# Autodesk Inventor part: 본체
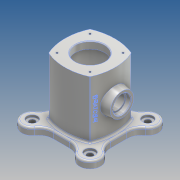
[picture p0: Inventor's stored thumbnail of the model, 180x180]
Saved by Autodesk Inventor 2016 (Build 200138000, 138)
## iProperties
Created: 2016-05
Part Number: 본체
Material: 알루미늄 6061
Document SubType Name: Modeling
Designer: Administrator
Density: 2.7 g/cm^3
Appearance: 알루미늄 - 평지
Mass: 1101.94 g
Surface Area: 864.846 cm^2
Volume: 408.127 cm^3
Author: Administrator
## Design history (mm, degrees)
sketch "스케치1" dims "d0" = 140
  geometry: L1 (-49, 49)-(49, 49); L2 (49, 49)-(49, -49); L3 (49, -49)-(-49, -49); L4 (-49, -49)-(-49, 49); L5 (-49, 49)-(49, -49); L6 (49, 49)-(-49, -49); L7 (0, 0)-(0, 49); L8 (0, 0)-(107.625, 107.625); L9 (0, 0)-(-94.165, 94.165); L10 (0, 0)-(-132.775, -132.775); L11 (0, 0)-(113.13, -113.13); L12 (0, 0)-(0, -49); A1 r 18 centre (49.497, 49.497) between (59.754, 34.706) and (34.706, 59.754); A2 r 18 centre (-49.497, 49.497) between (-34.706, 59.754) and (-59.754, 34.706); A3 r 18 centre (-49.497, -49.497) between (-59.754, -34.706) and (-34.706, -59.754); A4 r 18 centre (49.497, -49.497) between (34.706, -59.754) and (59.754, -34.706); A5 r 25 centre (-74, 14.162) between (-49, 14.162) and (-60.503, 35.205); A6 r 25 centre (-74, -14.162) between (-60.503, -35.205) and (-49, -14.162); A7 r 25 centre (-14.162, -74) between (-14.162, -49) and (-35.205, -60.503); A8 r 25 centre (14.162, -74) between (35.205, -60.503) and (14.162, -49); A9 r 25 centre (74, -14.162) between (49, -14.162) and (60.503, -35.205); A10 r 25 centre (74, 14.162) between (60.503, 35.205) and (49, 14.162); A11 r 25 centre (14.162, 74) between (14.162, 49) and (35.205, 60.503); A12 r 25 centre (-14.162, 74) between (-35.205, 60.503) and (-14.162, 49); 1 further point
  constraints: 32 point on circle, 24 end point, 16 tangent, 12 centre point, 12 point on line, 4 midpoint, 2 parallel, 1 coincident, 1 horizontal, 1 perpendicular, 14 other
  dimensions: "d1" = 98 distance of L2.end L3.end; "d2" = 98 distance of L1.end L2.end; "d5" = 45 deg angle of L7 L8; "d6" = 45 deg angle of L9 L7; "d7" = 36 diameter of A1; "d8" = 36 diameter of A2; "d9" = 45 deg angle of L10 L12; "d10" = 45 deg angle of L12 L11; "d11" = 36 diameter of A3; "d12" = 36 diameter of A4; "d13" = 50 diameter of A5; "d14" = 50 diameter of A6; "d15" = 50 diameter of A7; "d16" = 50 diameter of A8; "d17" = 50 diameter of A9; "d18" = 50 diameter of A10; "d19" = 50 diameter of A11; "d20" = 50 diameter of A12
extrude "돌출1" new body sketch "스케치1" distance "d21" = 12; taper "d22" = 0 deg
sketch "스케치2"
  geometry: A1 r 18 centre (49.497, 49.497) between (59.754, 34.706) and (34.706, 59.754) reference; A2 r 18 centre (-49.497, 49.497) between (-34.706, 59.754) and (-59.754, 34.706) reference; A3 r 18 centre (-49.497, -49.497) between (-59.754, -34.706) and (-34.706, -59.754) reference; A4 r 18 centre (49.497, -49.497) between (34.706, -59.754) and (59.754, -34.706) reference; 5 further points
  constraints: 4 coincident
hole "구멍1" sketch "스케치2" at (-49.497, 49.497), (49.497, 49.497), (49.497, -49.497), (-49.497, -49.497) diameter "d23" = 10; stored, may be unused: countersink angle "d27" = 90 deg, drill point angle "d29" = 0 deg; dims "d24" = 6, "d25" = 18, "d26" = 4, "d28" = 8
sketch "스케치3"
  geometry: L1 (14.162, 49)-(-14.162, 49) reference; L2 (-14.162, -49)-(14.162, -49) reference; L3 (0, -49)-(0, 49); L4 (35.355, -35.355)-(-35.355, 35.355); L5 (-35.355, -35.355)-(35.355, 35.355); L6 (-25.756, 0)-(24.103, 0); A1 r 85.579 centre (42.579, 0) between (-35.355, 35.355) and (-35.355, -35.355); A2 r 85.579 centre (0, 42.579) between (-35.355, -35.355) and (35.355, -35.355); A3 r 90.136 centre (0, -47.557) between (35.355, 35.355) and (-35.355, 35.355); A4 r 85.579 centre (-42.579, 0) between (35.355, -35.355) and (35.355, 35.355); 8 further points
  constraints: 12 point on circle, 8 end point, 5 midpoint, 4 centre point, 2 coincident, 2 horizontal alignment, 2 symmetric about line, 2 vertical alignment, 1 horizontal, 1 point on line
  dimensions: "d36" = 45 deg angle of L5 L3; "d37" = 45 deg angle of L4 L3; "d38" = 100 distance of L4.start L4.end; "d39" = 100 distance of L5.start L5.end; "d42" = 86 distance of point (43, 0) point (-43, 0); "d43" = 86 distance of point (0, -43) point (0, 43)
extrude "돌출2" join sketch "스케치3" distance "d44" = 98; taper "d45" = 0 deg
sketch "스케치4"
  geometry: L1 (15.743, 61)-(-55, 61); L2 (-55, 81)-(-55, 61); L3 (-34.706, 0)-(-14.162, 0) reference; L4 (-55, 81)-(-38.425, 83.923); L5 (-43, 61)-(-55, 61); L6 (-38.425, 61)-(-38.425, 83.923); L7 (-43, 12)-(-43, 110) reference; L8 (-38.425, 61)-(-43, 61); 1 further point
  constraints: 12 end point, 2 vertical, 1 collinear, 1 horizontal, 1 parallel, 1 point on line
  dimensions: "d46" = 55 distance from line of L2 point (0, 0); "d47" = 61 distance between parallel lines of L1 L3; "d49" = 40 diameter of L2.start L1; "d54" = 100 deg angle of L7 L4; "d59" = 38.42505 distance from line of L6 point (0, 0)
revolve "회전1" sketch "스케치4" stored, may be unused: angle "d53" = 90 deg
sketch "스케치6"
  geometry: C1 r 20 at (0, 0) reference; 2 further points
  constraints: 1 coincident
hole "구멍2" sketch "스케치6" at (0, 0) diameter "d60" = 25; stored, may be unused: countersink angle "d64" = 90 deg, drill point angle "d66" = 0 deg; dims "d61" = 6, "d62" = 30, "d63" = 8, "d65" = 30
sketch "스케치7"
  geometry: L1 (0, 148.847)-(0, -38.86); L2 (35, 98)-(25, 98); L3 (35.355, 110)-(-35.355, 110) reference; L4 (35, 98)-(35, 12); L5 (35, 12)-(25, 12); L6 (14.162, 0)-(34.706, 0) reference; L7 (25, 110)-(25, 98); L8 (25, 12)-(25, 0); L9 (25, 110)-(0, 110); L10 (25, 0)-(0, 0); L11 (14.162, 0)-(-14.162, 0) reference; L12 (0, 110)-(0, 0)
  constraints: 18 end point, 4 vertical, 3 point on line, 2 collinear, 2 horizontal, 1 midpoint
  dimensions: "d68" = 12 distance between parallel lines of L2 L3; "d70" = 70 diameter of L4 L1; "d71" = 12 distance between parallel lines of L5 L6; "d72" = 50 diameter of L8 L1; "d73" = 50 diameter of L7 L1
revolve "회전2" sketch "스케치7" stored, may be unused: angle "d74" = 90 deg
sketch "스케치8" dims "d75" = 80
  geometry: L1 (0, 0)-(85.458, -85.458); L2 (0, 0)-(102.239, 102.239); L3 (0, 0)-(19.754, 0); L4 (0, 0)-(0, -20.436); C1 r 25 at (0, 0) reference; 4 further points
  constraints: 8 end point, 1 coincident, 1 horizontal, 1 point on line, 1 vertical, 8 other
  dimensions: "d76" = 45 deg angle of L3 L1; "d77" = 45 deg angle of L2 L3; "d80" = 360 deg dimension on C1.centre point (28.284, -28.284) (derived)
hole "구멍3" sketch "스케치8" at (28.284, -28.284), (28.284, 28.284), (-28.284, 28.284), (-28.284, -28.284) diameter "d82" = 3.242; stored, may be unused: countersink angle "d86" = 90 deg, drill point angle "d88" = 118 deg; dims "d83" = 7, "d84" = 30, "d85" = 8, "d87" = 10
sketch "스케치9"
  geometry: L1 (0, 0)-(13.184, 0); L2 (0, 0)-(74.821, 74.821); C1 r 25 at (0, 0) reference; C2 r 25 at (0, 0) reference; C3 r 40 at (0, 0); C4 r 1.621 at (28.284, 28.284) reference; 4 further points
  constraints: 4 end point, 2 coincident, 1 centre point, 1 horizontal, 1 point on line, 5 other
  dimensions: "d89" = 80 diameter of C3; "d90" = 45 deg angle of L1 L2; "d93" = 360 deg dimension on C1.centre point (28.284, 28.284) (derived)
hole "구멍4" sketch "스케치9" at (28.284, 28.284), (-28.284, 28.284), (-28.284, -28.284), (28.284, -28.284) diameter "d95" = 3.242; stored, may be unused: countersink angle "d99" = 90 deg, drill point angle "d101" = 118 deg; dims "d96" = 7, "d97" = 30, "d98" = 8, "d100" = 10
chamfer "모따기1" distance "d102" = 1; stored, may be unused: second distance "d103" = 2, angle "d104" = 45 deg
fillet "모깎기1" dims "d105" = 3
fillet "모깎기2" dims "d106" = 3
node "작업 평면1"
sketch "스케치10"
  geometry: L1 (42.579, 15)-(42.579, 110) reference; L2 (67.497, 0)-(34.706, 0) reference; L3 (0, 0)-(0, 163.689); L4 (97.662, 61)-(-130.641, 61); L5 (34.248, 110)-(-34.285, 110) reference; 3 further points
  constraints: 4 end point, 1 horizontal, 1 vertical, 2 other
  dimensions: "d108" = 61 distance between parallel lines of L4 L2; "d109" = 49 distance from line of L5 point (-29, 61); "d110" = 29 distance from line of L3 point (-29, 61)
feature "엠보싱1" sketch "스케치10" dims "d111" = 0.5, "d112" = 0
node "솔리드1"
